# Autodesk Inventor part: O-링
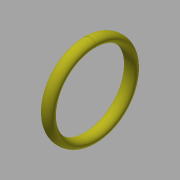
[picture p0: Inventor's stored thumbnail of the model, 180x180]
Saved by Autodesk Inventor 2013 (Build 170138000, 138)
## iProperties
Created: 2019-02
Part Number: O-링
Material: 고무
Document SubType Name: Modeling
Designer: mduedu
Density: 1 g/cm^3
Author: mduedu
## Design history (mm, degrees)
sketch "스케치1"
  geometry: L1 (-2.35, 0)-(2.35, 0); L2 (2.35, 0)-(2.35, 17); L3 (2.35, 17)-(-2.35, 17); L4 (-2.35, 17)-(-2.35, 0); L5 (-2.35, 14)-(2.35, 14); 3 further points; 1 other entity
  constraints: 10 end point, 4 horizontal, 2 parallel, 2 perpendicular, 2 point on line, 2 vertical, 1 coincident, 1 midpoint, 2 other
  dimensions: "d0" = 34 diameter of L3 L1; "d2" = 4.7 distance of L2.end L3.end; "d3" = 28 diameter of L5 L1
revolve "회전1" sketch "스케치1" stored, may be unused: angle "d4" = 90 deg
node "솔리드1"
